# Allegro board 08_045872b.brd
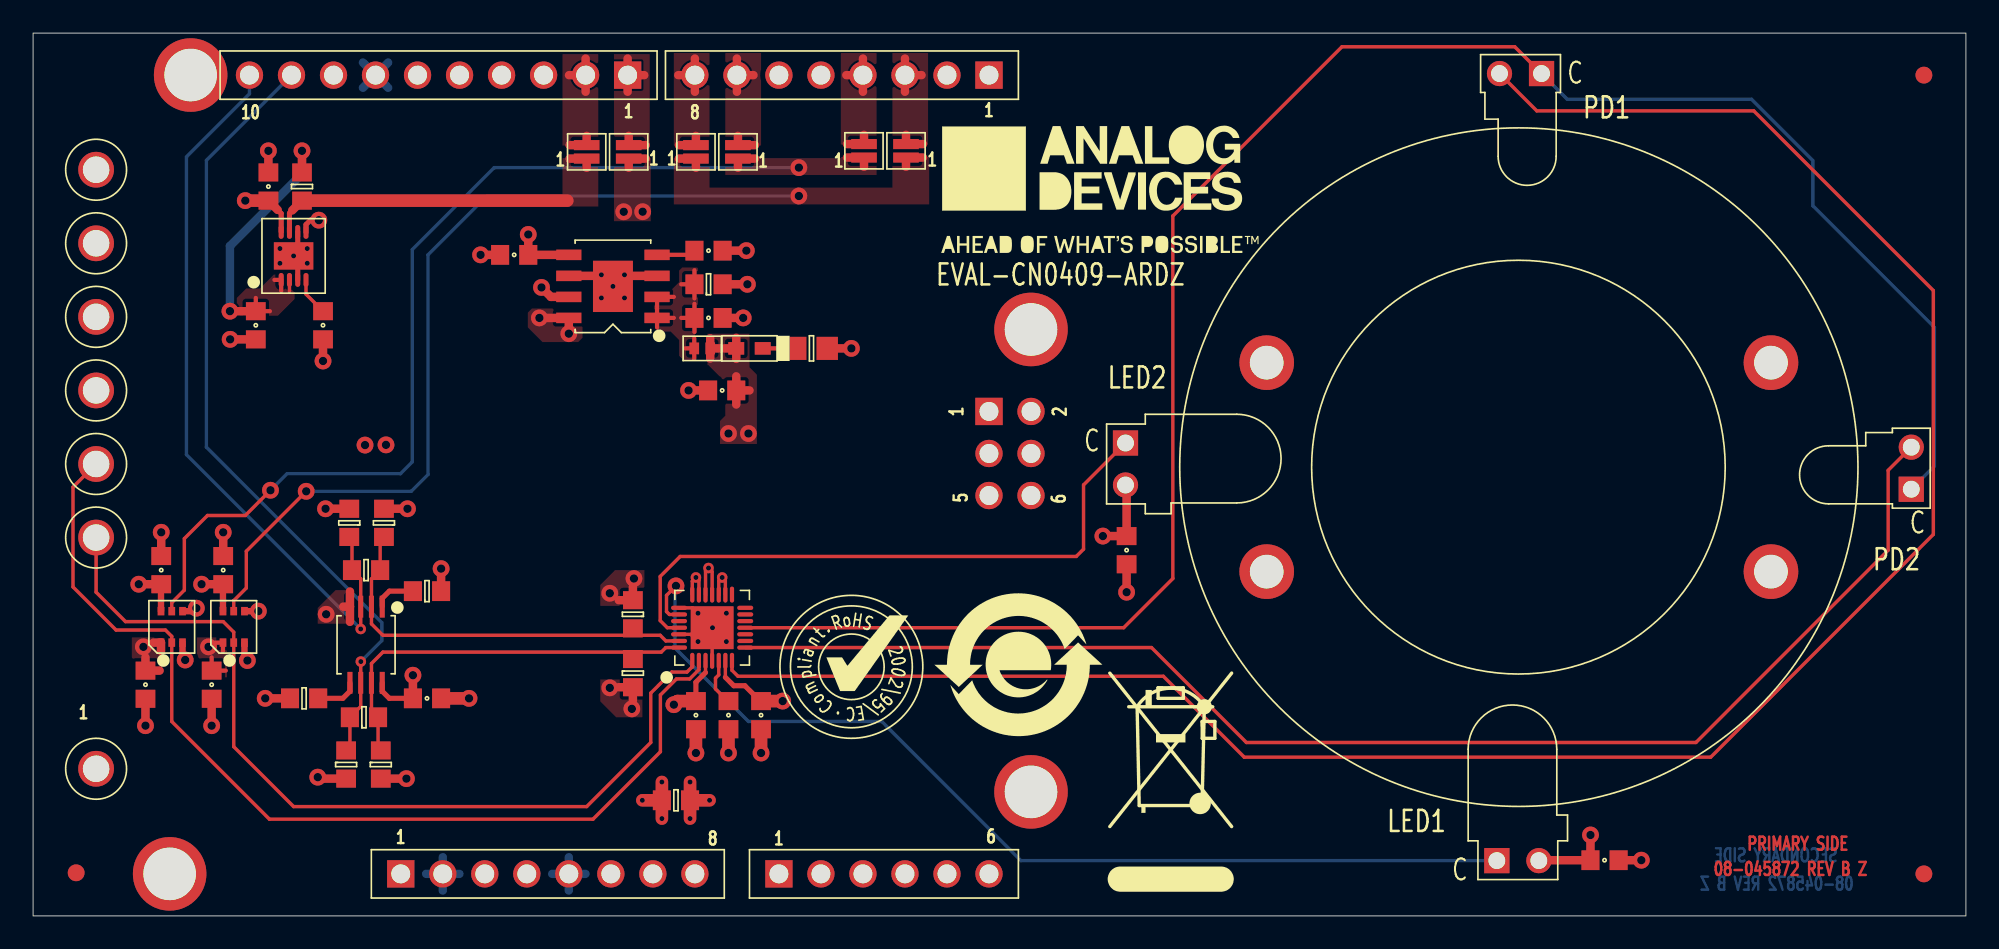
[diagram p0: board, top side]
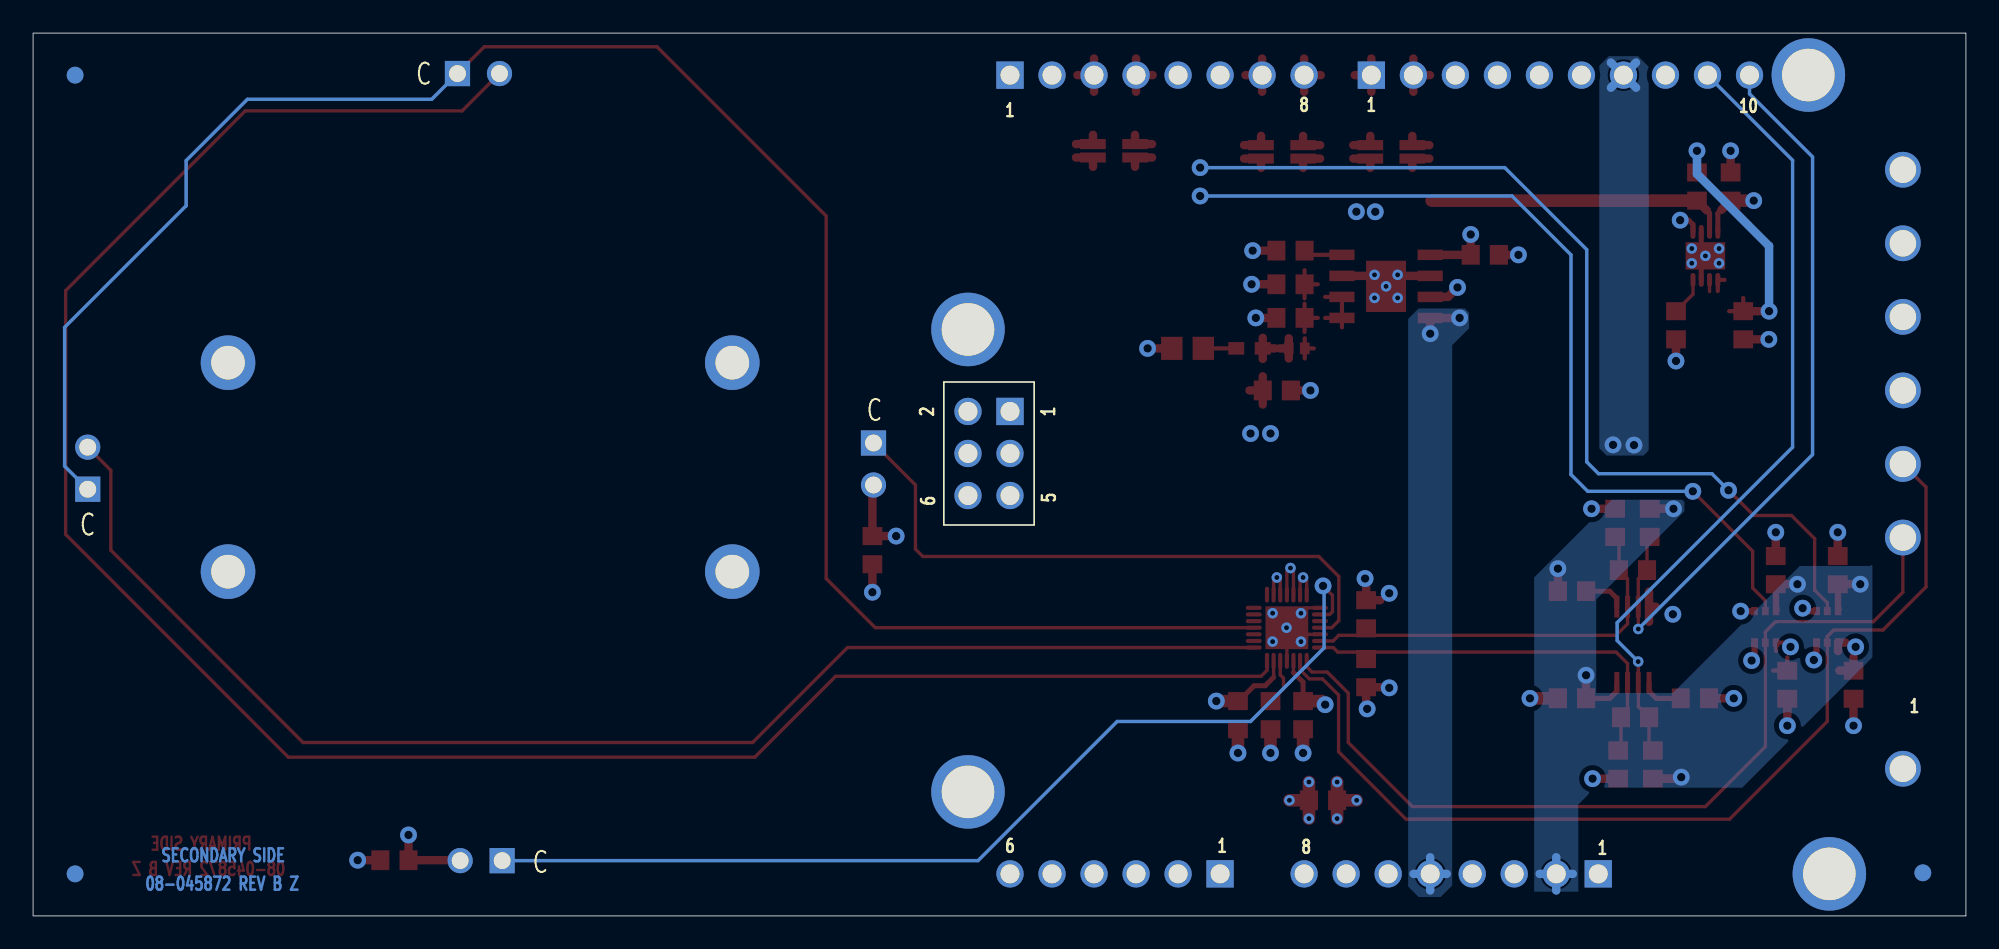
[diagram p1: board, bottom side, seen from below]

Outline 116.84 x 53.34 mm; copper layers: TOP, L2_GND, L3_POWER, BOTTOM. Coordinates in mm from the lower left corner of the outline.
Outline path: 0,53.34 116.84,53.34 116.84,0 0,0 0,53.34

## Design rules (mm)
constraint set DEFAULT: min track width 0.203

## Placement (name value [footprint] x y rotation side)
AGND  YEL  [CNLOOPTP]  3.81 36.2 0 top
C1  4.7uF  [C0603]  14.22 44.07 270 top
C2  1uF  [C0603]  66.1 22.1 270 top
C3  0.1uF  [C0603]  17.53 35.69 90 top
C4  1uF  [C0603]  95 3.37 0 top
C5  4.7uF  [C0603]  13.46 35.69 90 top
C6  4.7uF  [C0603]  29.08 39.94 0 top
C7  0.1uF  [C0603]  40.83 40.2 180 top
C8  4.7uF  [C0603]  40.83 36.13 180 top
C9  1uF  [C0603]  42.04 12.13 270 top
C10  1uF  [C0603]  44.01 12.13 90 top
C11  0.1uF  [C0603]  40.07 12.13 90 top
C12  4.7uF  [C0603]  41.66 31.75 0 top
C13  0.1uF  [C0603]  7.75 20.89 270 top
C14  0.1uF  [C0603]  6.79 13.97 90 top
C15  0.1uF  [C0603]  11.49 20.89 270 top
C16  0.1uF  [C0603]  10.8 13.97 90 top
C17  0.01uF  [C0603]  23.81 13.14 180 top
D1  SFH229  [DTHD150H248]  91.19 50.9 180 top
D2  SFH229  [DTHD150H248]  113.54 25.78 90 top
DGND  YEL  [CNLOOPTP]  3.81 8.89 0 top
DS1  SFH4556  [LEDTHD217H319]  66.04 28.57 270 top
DS2  SFH4556  [LEDTHD217H319]  88.48 3.34 0 top
DS3  SML-310MTT86  [LED0603]  43.31 34.29 180 top
E1  600OHM  [L0402]  40.45 34.29 0 top
GPIO0  YEL  [CNLOOPTP]  3.81 22.86 0 top
GPPIO1  YEL  [CNLOOPTP]  3.81 27.3 0 top
NOREF  -  []  -12.06 -17.91 0 top
NOREF#2  -  []  -148.78 -263.14 0 top
NOREF#3  -  []  49.47 15.05 0 top
NOREF#4  -  []  0 0 0 top
NOREF#5  -  [unnamed#2]  114.3 2.54 0 top
NOREF#6  -  []  158.62 -29.08 90 top
NOREF#7  -  []  116.84 0 0 top
NOREF#8  -  []  -90.55 135.76 0 top
NOREF#9  -  []  0 53.34 0 top
NOREF#10  -  []  59.56 15.18 0 top
NOREF#11  -  [unnamed#2]  60.33 7.49 0 top
NOREF#12  -  [unnamed#2]  74.57 20.8 0 top
NOREF#13  -  []  126.87 -58.74 0 top
NOREF#14  -  []  -148.78 -263.14 0 top
NOREF#15  -  []  -148.78 -263.14 0 top
NOREF#16  -  []  64.52 43.88 0 top
NOREF#17  -  [unnamed#2]  60.33 35.43 0 top
NOREF#18  -  [unnamed#2]  9.53 50.81 0 top
NOREF#19  -  [unnamed#2]  105.06 20.8 0 top
NOREF#20  -  []  -209.3 -257.68 0 top
NOREF#21  -  []  0 53.34 0 top
NOREF#22  -  [unnamed#2]  114.3 50.8 0 top
NOREF#23  -  []  101.22 136.27 0 top
NOREF#24  -  []  8.26 2.54 0 top
NOREF#25  -  []  78.04 18.35 0 top
NOREF#26  -  [unnamed#2]  74.57 33.43 0 top
NOREF#27  -  []  172.59 75.82 180 top
NOREF#28  -  []  8.26 2.54 0 top
NOREF#29  -  []  0 0 0 top
NOREF#30  -  [unnamed#2]  2.6 2.6 0 top
NOREF#31  -  []  -95.69 -120.14 0 top
NOREF#32  -  []  116.84 0 90 top
NOREF#33  -  []  -12.19 70.48 270 top
NOREF#34  -  [unnamed#2]  8.26 2.54 0 top
NOREF#35  -  [unnamed#2]  105.06 33.43 0 top
NOREF#36  -  []  189.48 97.41 0 top
NOREF#37  -  []  254.64 -37.97 0 top
NOREF#38  -  [unnamed#2]  114.3 50.8 180 bottom
NOREF#39  -  [unnamed#2]  2.6 2.6 180 bottom
NOREF#40  -  [unnamed#2]  114.3 2.54 180 bottom
P3  SSQ-106-03-G-S  [CNSAMTECSSQ-106-XX-X-S]  45.09 2.54 0 top
P4  SSQ-108-03-G-S  [CNSAMTECSSQ-108-XX-X-S]  22.23 2.54 0 top
P5  -  [JPSLD02]  36 46.16 90 top
P6  SSQ-110-03-G-S  [CNSAMTECSSQ-110-XX-X-S]  35.94 50.8 180 top
P7  SSQ-108-03-G-S  [CNSAMTECSSQ-108-XX-X-S]  57.79 50.8 180 top
P8  -  [JPSLD02]  33.46 46.16 90 top
P9  SSQ-103-03-G-D  [CNSAMTECSSQ-103-XX-X-D]  57.79 30.48 270 bottom
P10  -  [JPSLD02]  52.77 46.23 90 top
P11  -  [JPSLD02]  50.23 46.23 90 top
P12  -  [JPSLD02]  42.61 46.16 90 top
P13  -  [JPSLD02]  40.07 46.16 90 top
R1  10K  [R0603]  16.26 44.07 270 top
R2  10K  [R0603]  23.81 19.62 0 top
R3  10K  [R0603]  40.83 38.16 0 top
R4  10K  [R0603]  36.26 18.22 90 top
R5  20  [R0805]  47.05 34.29 180 top
R6  4.99K  [R0603]  19.11 23.75 90 top
R7  10K  [R0603]  36.26 14.67 270 top
R8  4.99K  [R0603]  18.92 9.14 270 top
R9  10K  [R0603]  16.38 13.14 180 top
R10  4.99K  [R0603]  21.21 23.75 90 top
R11  4.99K  [R0603]  21.02 9.14 270 top
R12  0  [R0603]  20 12 0 top
R13  0  [R0603]  38.86 6.99 180 top
R14  0  [R0603]  20.13 20.89 0 top
U1  ADP7105ACPZ-3.3  [DFN8_3X3_PAD2_38X1_64]  15.75 39.88 0 top
U2  ADP7105ARDZ-1.8  [SO8NB-PAD3_1X2_41]  35.05 38.04 90 top
U3  ADPD105BCPZ  [QFN28_4X4_PAD2_6X2_6]  41.05 17.41 0 top
U4  LTC4313IMS8-3#PBF  [MSOP8]  20.13 16.38 180 top
U5  ADG3301BKSZ  [SC70-6]  12.13 17.46 0 top
U6  ADG3301BKSZ  [SC70-6]  8.38 17.46 0 top
UNK1.8V  YEL  [CNLOOPTP]  3.81 31.75 0 top
UNK3.3V  YEL  [CNLOOPTP]  3.81 40.64 0 top
UNK5V  YEL  [CNLOOPTP]  3.81 45.09 0 top

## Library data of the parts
AGND DGND GPIO0 GPPIO1 UNK1.8V UNK3.3V UNK5V = CNTP1P: User Part Number: UPN; Tolerance: N/A; alternate symbols: (); part number: CNTP1P_TH-YEL,E000945,CNLOOPTP; tolerance: N/A
C1 C5 C6 C8 C12 = CAP: Tolerance: 10; User Part Number: UPN; alternate symbols: (); part number: CAP_SM-4.7UF,6.3V,10,E010382,C0603; tolerance: 10
C2 C4 C9 C10 = CAP: Tolerance: 10; User Part Number: UPN; alternate symbols: (); part number: CAP_SM-1UF,16V,10,E006882,C0603; tolerance: 10
C3 C7 C11 C13-C16 = CAP: Tolerance: 10; User Part Number: UPN; alternate symbols: (); part number: CAP_SM-0.1UF,50V,10,E015248,C0603; tolerance: 10
C17 = CAP: Tolerance: 10; User Part Number: UPN; alternate symbols: (); part number: CAP_SM-0.01UF,25V,10,E012078,C0603; tolerance: 10
D1 D2 = DIOPHOTO: User Part Number: UPN; Tolerance: N/A; alternate symbols: DTHD150H248_RA; part number: DIOPHOTO_TH-SFH229,20V,N/A,E028603,DTHD150H248; tolerance: N/A
DS1 DS2 = DIOLED: User Part Number: UPN; Tolerance: N/A; alternate symbols: (LEDTHD217H319_RA); part number: DIOLED_TH-SFH4556,1.5V,N/A,E028315,LEDTHD217H319; tolerance: N/A
DS3 = DIOLED: Tolerance: N/A; User Part Number: UPN; alternate symbols: (); part number: DIOLED_SM-SML-310MTT86,2.8V,N/A,E001179,LED0603; tolerance: N/A
E1 = FERRITE: Tolerance: 25; User Part Number: UPN; alternate symbols: (L0402L); part number: FERRITE_SM-600OHM,25,E015362,L0402; tolerance: 25
P3 = CN6P: User Part Number: UPN; Tolerance: N/A; alternate symbols: (); part number: CN6P_TH-SSQ-106-03-G-S,E020477,CNSAMTECSSQ-106-XX-X-S; tolerance: N/A
P4 P7 = CN8P_A: User Part Number: UPN; Tolerance: N/A; alternate symbols: (); part number: CN8P_A_TH-SSQ-108-03-G-S,E020478,CNSAMTECSSQ-108-XX-X-S; tolerance: N/A
P5 P8 P10-P13 = NC2P: User Part Number: UPN; Tolerance: N/A; alternate symbols: (); part number: NC2P_SM-JPSLD02,E006230,JPSLD02; tolerance: N/A
P6 = CN10P: User Part Number: UPN; Tolerance: N/A; alternate symbols: (); part number: CN10P_TH-SSQ-110-03-G-S,E020479,CNSAMTECSSQ-110-XX-X-S; tolerance: N/A
P9 = CN6P: User Part Number: UPN; Tolerance: N/A; alternate symbols: (); part number: CN6P_TH-SSQ-103-03-G-D,E020488,CNSAMTECSSQ-103-XX-X-D; tolerance: N/A
R1-R4 R7 R9 = RES: Tolerance: 1; User Part Number: UPN; alternate symbols: (R0603L); part number: RES_SM-10K,E003671,1/10W,1,R0603; tolerance: 1
R5 = RES: Tolerance: 1; User Part Number: UPN; alternate symbols: (R0805L); part number: RES_SM-20,E003563,1/8W,1,R0805; tolerance: 1
R6 R8 R10 R11 = RES: Tolerance: 1; User Part Number: UPN; alternate symbols: (R0603L); part number: RES_SM-4.99K,E003726,1/10W,1,R0603; tolerance: 1
R12-R14 = RES: Tolerance: 5; User Part Number: UPN; alternate symbols: (R0603L); part number: RES_SM-0,E006826,1/10W,5,R0603; tolerance: 5
U1 = ADP7105: Tolerance: N/A; User Part Number: UPN; alternate symbols: (); part number: ADP7105_SM-ADP7105ACPZ-3.3,E019351,DFN8_3X3_PAD2_38X1_64; tolerance: N/A
U2 = ADP7105: Tolerance: N/A; User Part Number: UPN; alternate symbols: (); part number: ADP7105_SM-ADP7105ARDZ-1.8,E021546,SO8NB-PAD3_1X2_41; tolerance: N/A
U3 = ADPD10X_V2: Tolerance: N/A; User Part Number: UPN; alternate symbols: (); part number: ADPD10X_V2_SM-ADPD105BCPZ,E028393,QFN28_4X4_PAD2_6X2_6; tolerance: N/A
U4 = LINLTC4313_V2: Tolerance: N/A; User Part Number: UPN; alternate symbols: (); part number: LINLTC4313_V2_SM-LTC4313IMS8-3#PBF,E031527,MSOP8; tolerance: N/A
U5 U6 = ADG3301: Tolerance: N/A; User Part Number: UPN; alternate symbols: (); part number: ADG3301_SM-ADG3301BKSZ,E010847,SC70-6; tolerance: N/A

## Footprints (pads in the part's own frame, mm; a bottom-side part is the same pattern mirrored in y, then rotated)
C0603
  rect 1.092x1.194 smd: 1(-0.851,0) 2(0.851,0)
CNLOOPTP
  round 2.159 hole 1.6: 1(0,0)
CNSAMTECSSQ-103-XX-X-D
  rect 1.651x1.651 hole 1.143: 1(0,0)
  round 1.651 hole 1.143: 2(0,-2.54) 3(2.54,0) 4(2.54,-2.54) 5(5.08,0) 6(5.08,-2.54)
CNSAMTECSSQ-106-XX-X-S
  rect 1.651x1.651 hole 1.143: 1(0,0)
  round 1.651 hole 1.143: 2(2.54,0) 3(5.08,0) 4(7.62,0) 5(10.16,0) 6(12.7,0)
CNSAMTECSSQ-108-XX-X-S
  rect 1.651x1.651 hole 1.143: 1(0,0)
  round 1.651 hole 1.143: 2(2.54,0) 3(5.08,0) 4(7.62,0) 5(10.16,0) 6(12.7,0) 7(15.24,0) 8(17.78,0)
CNSAMTECSSQ-110-XX-X-S
  rect 1.651x1.651 hole 1.143: 1(0,0)
  round 1.651 hole 1.143: 2(2.54,0) 3(5.08,0) 4(7.62,0) 5(10.16,0) 6(12.7,0) 7(15.24,0) 8(17.78,0) 9(20.32,0) 10(22.86,0)
DFN8_3X3_PAD2_38X1_64
  oval 0.305x0.838 smd: 1(-0.75,-1.45) 2(-0.25,-1.45) 3(0.25,-1.45) 4(0.75,-1.45) 5(0.75,1.45) 6(0.25,1.45) 7(-0.25,1.45) 8(-0.75,1.45)
  rect 2.388x1.651 smd: PAD(0,0)
DTHD150H248
  round 1.524 hole 1.016: A(2.54,0)
  rect 1.524x1.524 hole 1.016: C(0,0)
JPSLD02
  rect 0.61x1.549 smd: 1(-0.406,0) 2(0.406,0)
L0402
  rect 0.584x0.711 smd: 1(-0.483,0) 2(0.483,0)
LED0603
  rect 0.965x0.762 smd: A(0.8,0) C(-0.8,0)
LEDTHD217H319
  round 1.524 hole 1.016: A(2.54,0)
  rect 1.524x1.524 hole 1.016: C(0,0)
MSOP8
  rect 0.305x1.321 smd: 1(-0.975,-2.3) 2(-0.325,-2.3) 3(0.325,-2.3) 4(0.975,-2.3) 5(0.975,2.3) 6(0.325,2.3) 7(-0.325,2.3) 8(-0.975,2.3)
QFN28_4X4_PAD2_6X2_6
  oval 0.254x0.965 smd: 1(-1.2,-2) 2(-0.8,-2) 3(-0.4,-2) 4(0,-2) 5(0.4,-2) 6(0.8,-2) 7(1.2,-2) 15(1.2,2) 16(0.8,2) 17(0.4,2) 18(0,2) 19(-0.4,2) 20(-0.8,2) 21(-1.2,2)
  oval 0.965x0.254 smd: 8(2,-1.2) 9(2,-0.8) 10(2,-0.4) 11(2,0) 12(2,0.4) 13(2,0.8) 14(2,1.2) 22(-2,1.2) 23(-2,0.8) 24(-2,0.4) 25(-2,0) 26(-2,-0.4) 27(-2,-0.8) 28(-2,-1.2)
  rect 2.591x2.591 smd: PAD(0,0)
R0603
  rect 1.092x1.194 smd: 1(-0.851,0) 2(0.851,0)
R0805
  rect 1.295x1.397 smd: 1(-0.953,0) 2(0.953,0)
SC70-6
  rect 0.406x0.508 smd: 1(-0.65,-0.95) 2(0,-0.95) 3(0.65,-0.95) 4(0.65,0.95) 5(0,0.95) 6(-0.65,0.95)
SO8NB-PAD3_1X2_41
  rect 0.635x1.524 smd: 1(-1.905,-2.667) 2(-0.635,-2.667) 3(0.635,-2.667) 4(1.905,-2.667) 5(1.905,2.667) 6(0.635,2.667) 7(-0.635,2.667) 8(-1.905,2.667)
  rect 3.099x2.413 smd: PAD(0,0)
unnamed#2
  round 1.016 smd: (0,0)

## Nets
1.8V: C10.2(N2) C11.2(N2) C12.2(N2) C14.2(N2) C16.2(N2) DS3.A(P) E1.2(N2) R4.2(N2) R7.2(N2) R9.2(N2) R10.2(N2) R11.2(N2) U3.3 U3.6 U5.1 U5.4 U6.1 U6.4 UNK1.8V.1
3.3V: C2.1 C4.1 C5.2(N2) DS1.A(P) DS2.A(P) R1.1 U1.1(VOUT) U1.2 UNK3.3V.1
5V_ARDUINO: C1.2(N2) C6.2(N2) P4.5 U1.5 U1.8 U2.5 U2.8 UNK5V.1
AGND: AGND.1(N1) C1.1 C2.2(N2) C3.1 C4.2(N2) C5.1 C6.1 C7.1 C8.1 C9.2(N2) C10.1 C11.1 C12.1 R5.1 R13.1 U1.3 U1.6 U1.PAD U2.3 U2.6 U2.PAD U3.4 U3.16 U3.17 U3.18 U3.19 U3.20 U3.21 U3.22 U3.26 U3.PAD
DGND: C13.1 C14.1 C15.1 C16.1 C17.1 DGND.1(N1) P4.6 P4.7 P6.7 P9.6(N6) R13.2(N2) U4.4 U5.3 U6.3
GPIO0: GPIO0.1(N1) U3.1 U5.2
GPIO0_ARD: P10.1 P13.1 U5.5(Y)
GPIO1: GPPIO1.1(N1) U3.2 U6.2
GPIO1_ARD: P11.1 P12.1 U6.5(Y)
IOREF: C13.2(N2) C15.2(N2) C17.2(N2) P4.2 R2.2(N2) R6.2(N2) R8.2(N2) U4.8(VCC) U5.6 U6.6
LEDX1: DS2.C U3.23
LEDX2: DS1.C U3.25
PD1: D1.A(P) U3.7
PD2: D2.A(P) U3.8
PD_COM: D1.C D2.C U3.11
PG_1.8V: P5.1 R3.2(N2) U2.7
PG_3.3V: P8.1 R1.2(N2) U1.7
SCL: R4.1 R10.1 R14.2(N2) U3.27 U4.2
SCL_ARD: P6.10 R6.1 R14.1 U4.3
SDA: R7.1 R11.1 R12.2(N2) U3.28 U4.7
SDA_ARD: P6.9(N9) R8.1 R12.1 U4.6
UNNAMED_2_ADP7105_I12_SENSE: C8.2(N2) E1.1 R3.1 U2.1(VOUT) U2.2
UNNAMED_2_ADP7105_I12_SS: C7.2(N2) U2.4
UNNAMED_2_ADP7105_I29_SS: C3.2(N2) U1.4
UNNAMED_2_ADPD10XV2_I33_VREF: C9.1 U3.5(VREF)
UNNAMED_2_DIOLED_I63_N: DS3.C R5.2(N2)
UNNAMED_3_CN8PA_I12_N3: P7.3 P10.2(N2)
UNNAMED_3_CN8PA_I12_N4: P7.4 P11.2(N2)
UNNAMED_3_CN8PA_I12_N7: P7.7 P12.2(N2)
UNNAMED_3_CN8PA_I12_N8: P7.8(N8) P13.2(N2)
UNNAMED_3_CN10P_I18_N1: P5.2(N2) P6.1
UNNAMED_3_CN10P_I18_N2: P6.2 P8.2(N2)
UNNAMED_3_LINLTC4313V2_I104_ENA: R2.1 U4.1
UNNAMED_3_LINLTC4313V2_I104_REA: R9.1 U4.5

Pads without a net: P3 1 2 3 4 5 6; P4 1 3 4 8; P6 3 4 5 6 8; P7 1 2 5 6; P9 1 2 3 4 5; U3 9 10 12 13 14 15 24

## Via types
v1: diameter 0.635, hole 0.305, TOP to BOTTOM, 26 vias
v2: diameter 1.016, hole 0.508, TOP to BOTTOM, 62 vias

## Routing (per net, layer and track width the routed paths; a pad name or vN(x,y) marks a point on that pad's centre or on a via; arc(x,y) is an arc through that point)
1.8V: length 30.2
  TOP w0.203: U3.6 41.85,14.41 ; 40.65,14.7 U3.3
  TOP w0.254: 11.48,16 U5.1 11.02,16.51 ; 11.65,14.82 C16.2 10.8,15.62
  TOP w0.305: C10.2 43.95,12.98 43.03,13.91 42.36,13.91 41.85,14.41 ; C11.2 40.07,14.12 40.65,14.7
  TOP w0.381: U5.4 v2(13.62,18.41) ; U6.4 9.69,18.41 v2(9.87,18.59)
  TOP w0.508: R9.2 v2(14.03,13.14) ; 7.73,16 U6.1 7.27,16.51 ; 40.93,33.68 E1.2 ; E1.2 41.48,34.29 ; E1.2 40.93,34.9 ; 42.51,33.65 DS3.A ; DS3.A 41.77,34.29 ; DS3.A 42.51,34.93 ; C12.2 42.51,32.6 ; C12.2 43.31,31.75 ; C12.2 42.51,30.9 ; R11.2 v2(22.57,8.29) ; 35.41,19.08 R4.2 36.26,19.88 ; 36.26,13.02 R7.2 35.41,13.82 ; 7.65,14.82 C14.2 6.79,15.62 ; R10.2 v2(22.63,24.6)
  TOP w0.762: v2(38.73,12.76) 38.95,12.98 C11.2 ; C10.2 v2(45.31,12.98)
  vias: v2(6.67,16.26) v2(10.6,16.26) v2(34.86,19.49) v2(34.86,13.78) v2(36.2,12.51) v2(36.32,20.38) v2(42.04,29.15) v2(43.24,29.15)
3.3V: length 27
  TOP w0.203: 15.5,37.72 U1.2
  TOP w0.254: 15,37.75 U1.1 14.59,38.43 ; 14.31,36.54 C5.2 13.46,37.34
  TOP w0.508: C5.2 v2(11.9,36.54) ; R1.1 v2(16.26,46.23) ; DS1.A 66.1,25.97 C2.1 v2(64.67,22.95) ; v2(94.15,4.89) C4.1 91.05,3.37 DS2.A
  BOTTOM w0.508: v2(16.26,46.23) 16.26,44.83 11.9,40.47 v2(11.9,36.54)
5V_ARDUINO: length 15.4
  TOP w0.305: v2(17.27,42.04) 16.76,42.04 16.5,41.77 U1.5 ; 14.78,42.66 15,42.44 U1.8
  TOP w0.508: v2(32.38,35.18) U2.8 v2(30.61,36.13) ; C1.2 14.78,42.66 ; v2(29.93,41.17) C6.2 U2.5
  TOP w0.762: C1.2 v2(12.83,43.22)
  BOTTOM w0.508: 32.38,1.54 P4.5 ; P4.5 33.39,2.54 ; P4.5 31.38,2.54 ; P4.5 32.38,3.54
AGND: length 41.9
  TOP w0.203: U3.19 40.65,20.84 v1(40.83,21.02) 41.05,20.8 U3.18 ; v1(40.2,18.29) 39.87,18.61 U3.22 ; U3.17 41.45,20.24 v1(41.66,20.45) 41.85,20.25 U3.16 ; v1(40.2,16.57) 39.76,17.01 U3.26 ; U3.4 U3.PAD ; U3.21 39.85,20.23 v1(40.07,20.45) 40.25,20.27 U3.20
  TOP w0.305: U1.3 16,39.16 15.75,39.41 v1(15.75,39.88) 15.75,40.34 16,40.59 U1.6
  TOP w0.508: C8.1 v2(42.93,36.13) ; C7.1 v2(43.12,40.2) ; C3.1 v2(17.53,33.53) ; v1(35.05,38.04) 34.42,38.67 U2.6 ; C2.2 v2(66.1,19.56) ; v1(35.75,38.73) 35.81,38.67 U2.3 ; C5.1 v2(11.91,34.84) ; C4.2 v2(97.22,3.37) ; R5.1 v2(49.47,34.29) ; C12.1 v2(39.62,31.75) ; C6.1 v2(27.05,39.94) ; C1.1 v2(14.22,46.23)
  TOP w0.762: C11.1 v2(40.07,9.84) ; C10.1 v2(44.01,9.84) ; R13.1 v1(40.89,6.99) ; R13.1 v1(39.71,8.09) ; R13.1 v1(39.71,5.88) ; C9.2 v2(42.04,9.84)
  vias: v1(14.92,40.32) v1(14.92,39.43) v1(16.57,40.32) v1(16.57,39.43) v1(34.35,38.73) v1(34.35,37.34) v1(35.75,37.34) v1(41.07,17.41) v1(41.91,18.29) v1(41.91,16.57)
DGND: length 20
  TOP w0.381: U5.3 12.78,15.61 v2(12.95,15.43) ; v2(9.19,15.46) 9.03,15.63 U6.3
  TOP w0.508: C16.1 v2(10.8,11.49) ; 18.75,18.68 U4.4 ; U4.4 19.15,19.6 ; U4.4 19.15,17.77 ; C15.1 v2(11.49,23.18) ; C13.1 v2(7.75,23.18) ; C14.1 v2(6.79,11.49)
  TOP w0.762: C17.1 v2(26.35,13.14) ; R13.2 v1(36.83,6.99) ; R13.2 v1(38.01,8.09) ; R13.2 v1(38.01,5.88)
  BOTTOM w0.508: 19.94,51.56 P6.7 ; P6.7 21.46,51.56 ; P6.7 19.94,50.04 ; P6.7 21.46,50.04
  vias: v2(17.72,18.22) v2(20.07,28.45) v2(21.33,28.46)
GPIO0: length 54.4
  TOP w0.203: GPIO0.1 3.81,19.56 5.59,17.78 11.49,17.78 12.13,17.14 U5.2 12.13,10.22 15.75,6.6 33.46,6.6 37.34,10.48 37.34,13.46 38.61,14.73 39.52,14.73 39.85,15.06 U3.1
GPIO0_ARD: length 57.2
  TOP w0.203: U5.5 12.13,19.05 12.89,19.81 12.89,22.03 v2(16.51,25.65)
  TOP w0.508: 52.77,45.26 P10.1 53.8,45.82 ; 39.04,45.76 P13.1 40.07,45.2
  BOTTOM w0.203: v2(16.51,25.65) 22.86,25.65 23.88,26.67 23.88,39.94 27.43,43.5 v2(46.29,43.5)
GPIO1: length 61
  TOP w0.203: U3.2 40.25,14.88 39.69,14.32 38.89,14.32 37.92,13.35 37.92,9.92 33.85,5.84 14.29,5.84 8.38,11.75 U6.2 8.38,16.89 8,17.27 5.02,17.27 2.41,19.88 2.41,25.91 GPPIO1.1
GPIO1_ARD: length 61.8
  TOP w0.203: U6.5 8.38,18.92 9.14,19.69 9.14,22.8 10.54,24.19 12.83,24.19 v2(14.35,25.72)
  TOP w0.508: 49.2,45.82 P11.1 50.23,45.26 ; 42.61,45.2 P12.1 43.64,45.76
  BOTTOM w0.203: v2(14.35,25.72) 15.35,26.72 22.21,26.72 22.92,27.43 22.92,40.26 27.88,45.21 v2(46.29,45.21)
IOREF: length 18.4
  TOP w0.305: C17.2 21.53,13.14 21.1,13.57 U4.8
  TOP w0.381: C13.2 7.73,20.03 U6.6 ; U5.6 11.48,20.03 C15.2
  TOP w0.508: C17.2 v2(22.96,14.54) ; R6.2 v2(17.68,24.6) ; R2.2 24.66,20.98 v2(24.67,20.98) ; v2(17.21,8.38) 17.3,8.29 R8.2 ; C15.2 v2(10.19,20.04) ; C13.2 v2(6.39,20.04)
  BOTTOM w0.508: P4.2 25.77,2.54 ; P4.2 24.77,3.54 ; P4.2 24.77,1.54 ; P4.2 23.76,2.54
LEDX1: length 61.4
  TOP w0.203: U3.23 38.46,18.21 38.29,18.39 38.29,19.37 v2(38.86,19.94)
  BOTTOM w0.203: DS2.C 59.72,3.34 51.31,11.75 43.24,11.75 38.8,16.19 38.8,19.88 v2(38.86,19.94)
LEDX2: length 37.7
  TOP w0.203: DS1.C 63.5,26.04 63.5,22.16 63.06,21.72 39.12,21.72 37.91,20.51 37.91,17.84 38.34,17.41 U3.25
PD1: length 127.3
  TOP w0.203: D1.A 90.9,48.64 104.01,48.64 114.87,37.78 114.87,23.05 101.41,9.59 73.22,9.59 68.33,14.48 42.61,14.48 42.25,14.84 U3.7
PD2: length 83.1
  TOP w0.203: D2.A 112.14,26.92 112.14,22.1 100.52,10.48 73.34,10.48 67.61,16.21 U3.8
PD_COM: length 118.2
  TOP w0.203: D1.C 89.57,52.51 79.12,52.51 68.9,42.29 68.9,20.38 65.93,17.41 U3.11
  BOTTOM w0.203: D1.C 92.74,49.34 103.89,49.34 107.59,45.64 107.59,42.91 114.94,35.56 114.94,27.18 D2.C
PG_1.8V: length 5
  TOP w0.508: R3.2 v2(43.18,38.16) ; U2.7 31.31,37.4 v2(30.73,37.97) ; 36,45.2 P5.1 37.03,45.76
  vias: v2(35.71,42.54) v2(36.85,42.55)
PG_3.3V: length 19.8
  TOP w0.305: U1.7 15.5,42.46 15.67,42.63
  TOP w0.508: 33.46,45.2 P8.1 32.44,45.76 ; R1.2 15.67,42.63
  TOP w0.762: 32.3,43.22 R1.2
SCL: length 24.9
  TOP w0.203: R10.1 20.98,22.67 R14.2 20.45,20.37 U4.2 20.45,17.65 21.15,16.95 35.84,16.95 R4.1 36.68,16.95 37.91,16.95 38.25,16.61 U3.27
SCL_ARD: length 45.3
  TOP w0.203: R6.1 19.28,22.73 R14.1 19.8,20.37 U4.3 v1(19.8,17.34)
  BOTTOM w0.203: P6.10 13.08,49.67 9.27,45.86 9.27,27.87 v1(19.8,17.34)
SDA: length 24.8
  TOP w0.203: R11.1 20.85,10.16 R12.2 20.45,12.4 U4.7 20.45,15.25 21.15,15.94 35.84,15.94 R7.1 36.68,15.94 37.97,15.94 38.25,16.21 U3.28
SDA_ARD: length 48.2
  TOP w0.203: R8.1 19.15,10.22 R12.1 19.8,12.65 U4.6 19.8,15.17 19.81,15.18 v1(19.81,15.37)
  BOTTOM w0.203: v1(19.81,15.37) 21.08,16.64 21.08,17.72 10.48,28.32 10.48,45.66 P6.9
UNNAMED_2_ADP7105_I12_SENSE: length 10.5
  TOP w0.254: 39.42,34.29 E1.1 ; E1.1 39.97,34.9 ; E1.1 39.97,33.68 ; 37.72,36.83 U2.2 38.74,37.4 ; R3.1 39.98,39.01 ; R3.1 39.18,38.16 ; R3.1 39.98,37.31 ; 37.72,35.56 U2.1 ; U2.1 37.72,36.7 ; U2.1 38.74,36.13 ; 39.18,36.13 C8.2 ; C8.2 39.98,36.98 ; C8.2 39.98,35.28
UNNAMED_2_ADP7105_I12_SS: length 2.4
  TOP w0.254: C7.2 39.73,39.94 U2.4
UNNAMED_2_ADP7105_I29_SS: length 2.3
  TOP w0.203: U1.4 16.5,37.57 C3.2
UNNAMED_2_ADPD10XV2_I33_VREF: length 2.9
  TOP w0.203: U3.5 41.45,14.56 41.25,14.37 41.25,13.71 41.99,12.98 C9.1
UNNAMED_2_DIOLED_I63_N: length 2
  TOP w0.254: DS3.C R5.2
UNNAMED_3_CN8PA_I12_N3: length 4.6
  TOP w0.508: 52.77,47.19 P10.2 53.8,46.63 ; 52.71,49.8 P7.3 ; P7.3 53.71,50.8 ; P7.3 52.71,51.8
UNNAMED_3_CN8PA_I12_N4: length 4.6
  TOP w0.508: P7.4 50.16,51.8 ; P7.4 50.16,49.8 ; P7.4 49.16,50.8 ; 49.2,46.63 P11.2 50.23,47.19
UNNAMED_3_CN8PA_I12_N7: length 4.6
  TOP w0.508: 43.64,46.57 P12.2 42.61,47.13 ; 42.55,49.8 P7.7 ; P7.7 42.55,51.8 ; P7.7 43.55,50.8
UNNAMED_3_CN8PA_I12_N8: length 4.6
  TOP w0.508: 40.01,49.8 P7.8 ; P7.8 40.01,51.8 ; P7.8 39,50.8 ; 40.07,47.13 P13.2 39.04,46.57
UNNAMED_3_CN10P_I18_N1: length 4.6
  TOP w0.508: P6.1 35.94,51.8 ; P6.1 36.94,50.8 ; P6.1 35.94,49.8 ; 36,47.13 P5.2 37.03,46.57
UNNAMED_3_CN10P_I18_N2: length 4.6
  TOP w0.508: P6.2 33.4,51.8 ; P6.2 33.4,49.8 ; P6.2 32.4,50.8 ; 32.44,46.57 P8.2 33.46,47.13
UNNAMED_3_LINLTC4313V2_I104_ENA: length 2.5
  TOP w0.305: R2.1 21.53,19.62 21.1,19.19 U4.1
UNNAMED_3_LINLTC4313V2_I104_REA: length 2.6
  TOP w0.305: U4.5 19.15,13.57 18.72,13.14 R9.1

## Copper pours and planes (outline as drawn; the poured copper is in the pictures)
1.8V on TOP: 41.53,28.51 41.53,29.91 41.85,30.23 41.85,32.26 40.83,33.27 40.77,33.27 40.77,35.18 43.31,35.18 43.31,33.15 43.75,32.7 43.75,28.51
1.8V on TOP: 36.83,14.29 36.83,12 35.24,12 34.29,12.95 34.29,14.29
1.8V on TOP: 36.96,18.73 36.96,20.89 35.18,20.89 34.29,20 34.29,18.73
1.8V on TOP: 5.97,16.83 5.97,14.67 7.81,14.67 7.81,16.83
1.8V on TOP: 9.91,16.83 9.91,14.41 11.87,14.41 11.87,16.83
1.8V on L3_POWER: 1.84,32.51 1.84,6.48 3.18,5.14 9.65,5.14 10.73,4.06 46.36,4.06 47.37,5.08 47.37,28.07 45.72,29.72 40.64,29.72 35.31,24.38 25.84,24.38 22.42,27.81 22.42,28.57 21.72,29.27 11.05,29.27 7.05,33.27 2.6,33.27
3.3V on TOP: 12.32,37.34 12.32,36.26 14.8,36.26 15.81,37.27 15.81,37.66 15.68,37.78 15.68,38.29 15.11,38.86 14.67,38.86 13.72,37.91 12.89,37.91
3.3V on L3_POWER: 1.91,41.66 1.91,35.56 3.43,34.04 7.43,34.04 11.43,30.04 22.1,30.04 23.3,28.83 23.3,28.19 26.29,25.21 35.62,25.27 35.88,25.27 41.08,30.48 48.13,30.48 48.13,5.08 48.9,4.32 59.56,4.32 61.34,2.54 114.3,2.54 114.3,50.8 60.07,50.8 58.17,48.89 46.48,48.89 46.01,48.42 46.01,38.26 44.48,36.73 37.24,36.73 36.39,35.88 34.86,35.88 34.48,35.5 34.48,33.34 33.66,32.51 26.48,32.51 18.22,40.77 16.51,40.77 15.43,41.85 12.07,41.85 11.43,42.48 2.73,42.48
5V_ARDUINO on TOP: 32.96,36.7 30.16,36.7 29.91,36.45 29.91,35.56 30.8,34.67 32.96,34.67 33.21,34.92 33.21,36.45
5V_ARDUINO on BOTTOM: 33.08,36.7 30.29,36.7 30.04,36.45 30.04,35.5 31.05,34.48 31.05,1.84 31.75,1.14 33.08,1.14 33.72,1.78 33.72,36.07
5V_ARDUINO on L3_POWER: 2.1,48.26 10.54,48.26 11.68,49.4 30.99,49.4 31.81,48.58 31.81,42.16 28.83,39.18 28.83,37.4 29.53,36.7 32.19,36.7 33.72,35.18 33.72,33.72 33.27,33.27 26.83,33.27 18.57,41.53 16.92,41.53 15.84,42.61 12.45,42.61 11.75,43.31 2.1,43.31 1.52,43.88 1.52,47.69
AGND on L2_GND: 115.19,1.4 115.44,1.65 115.44,51.69 115.19,51.94 1.65,51.94 1.4,51.69 1.4,25.78 5.78,25.78 10.22,30.23 52.77,30.23 55.05,32.51 61.4,32.51 62.99,30.92 62.99,23.3 61.66,21.97 32.7,21.97 31.88,21.15 31.88,10.35 32.7,9.53 38.29,9.53 39.12,8.7 39.12,1.4
DGND on TOP: 17.21,18.61 17.21,17.65 19.3,17.65 19.3,19.68 18.29,19.68
DGND on BOTTOM: 19.81,51.94 21.59,51.94 22.16,51.37 22.16,28.26 21.72,27.81 19.49,27.81 19.18,28.13 19.18,51.31
DGND on L2_GND: 37.91,8.76 32.32,8.76 31.12,9.97 31.12,21.53 32.32,22.73 61.28,22.73 62.1,23.56 62.1,30.67 61.02,31.75 55.44,31.75 53.15,29.46 10.6,29.46 6.16,25.02 1.4,25.02 1.4,1.33 38.35,1.33 38.35,8.32
GPIO0_ARD on TOP: 38.73,42.99 38.73,45.78 40.89,45.78 40.89,44.01 51.94,44.01 51.94,45.85 54.17,45.85 54.17,42.99
GPIO1_ARD on TOP: 41.85,44.58 41.85,45.78 48.83,45.78 48.83,45.85 50.99,45.85 50.99,44.58
IOREF on BOTTOM: 23.43,1.46 23.43,6.73 22.42,7.75 13.53,7.75 5.65,15.62 5.65,21.27 5.78,21.15 10.03,21.15 17.72,13.46 22.35,13.46 22.35,19.11 17.02,24.45 17.02,25.15 21.4,25.15 26.1,20.45 26.1,1.46
IOREF on L3_POWER: 10.99,19.62 10.99,21.08 5.97,21.08 5.46,20.57 5.46,19.37 10.73,19.37
PG_1.8V on TOP: 35.12,46.04 35.12,41.97 37.34,41.97 37.34,46.04
PG_1.8V on L3_POWER: 29.65,38.73 29.65,37.78 29.97,37.46 32.83,37.46 33.34,36.96 36.2,36.96 36.85,37.61 44.12,37.61 45.05,38.54 45.05,49.31 43.94,50.42 43.94,51.44 43.43,51.94 35.88,51.94 32.83,48.89 32.83,41.91
PG_3.3V on TOP: 32,45.78 32,42.86 34.16,42.86 34.16,45.78
UNNAMED_2_ADP7105_I12_SENSE on TOP: 38.54,35.31 39.05,34.8 39.05,33.85 39.37,33.53 40.07,33.53 40.2,33.66 40.2,39.12 40.13,39.18 39.24,39.18 39.05,38.99 39.05,38.29 38.67,37.91 37.53,37.91 37.53,35.56 37.78,35.31
UNNAMED_3_CN8PA_I12_N3 on TOP: 51.94,52.13 51.94,46.61 54.1,46.61 54.1,52.13
UNNAMED_3_CN8PA_I12_N4 on TOP: 48.83,52.13 48.83,46.29 50.99,46.29 50.99,52.13
UNNAMED_3_CN8PA_I12_N7 on TOP: 41.85,52.13 41.85,46.55 44.01,46.55 44.01,52.13
UNNAMED_3_CN8PA_I12_N8 on TOP: 38.73,52.13 38.73,46.29 40.89,46.29 40.89,52.13
UNNAMED_3_CN10P_I18_N1 on TOP: 35.12,52.07 35.12,46.55 37.27,46.55 37.27,52.07
UNNAMED_3_CN10P_I18_N2 on TOP: 32,52.07 32,46.23 34.16,46.23 34.16,52.07

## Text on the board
BOTTOM: SECONDARY SIDE | 08-045872 REV B Z
Ref Des/Silkscreen Bottom: 1
User.Comments: SEE NOTE #7 | (5 PLACES) | SECONDARY SIDE | PRIMARY SIDE | SEE NOTE #6 | (4 PLACES) | 7.  DO NOT CUT EXCESS PINS ON CONNECTORS P3, P4, P6, P7, AND P9. | 6.  BEND LED'S PINS OF SFH229 AND SFH4556 BY 2.5 MM | SEE DETAIL BELOW: | (2.5 MM)
TOP: 08-045872 REV B Z | PRIMARY SIDE
Ref Des/Silkscreen Top: 1 | EVAL-CN0409-ARDZ | LED2 | LED1 | PD1 | PD2
PAGE_OUTLINE: 10MAR17 | B | CHANGES AS PER ECR-074043 | 08DEC17 | G. ARINUELO | ADP107, ADP105
DIMENSION: 1 | 2 | (REF) | " " | DIA MAX | SEE NOTE 15 | 09 | B
User.15: ROHS COMPLIANCE NOTE: | HOMOGENOUS MATERIALS IN THIS BOARD SHALL BE COMPLIANT | THE EU RoHS DIRECTIVE 2002/95/EC | PER IPC-4552 LATEST REVISION | 16.    BOARDS TO BE PANELIZED AND SHIPPED INTACT.
User.17: L2 GND | 08-      -07
User.18: L3 POWER | 08-      -08
User.45: FIGURE | SIZE | 12.0 | 20.0 | 40.0 | 45.0 | 63.0 | 80.0 | 125.0 | PLATED | NON-PLATED | FINISHED HOLES IN MILS | ALL UNITS ARE IN MILS | QTY | 26 | 61 | 8 | 38 | 7 | 4 | 148 | TOLERANCE/NOTES | TOTAL HOLES:
